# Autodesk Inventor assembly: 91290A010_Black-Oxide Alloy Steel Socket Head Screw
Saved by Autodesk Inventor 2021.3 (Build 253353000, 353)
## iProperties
Created: 2022-04
Part Number: 91290A010_Black-Oxide Alloy Steel Socket Head Screw
Document SubType Name: Assembly
Designer: Administrator
Title: 91290A010_Black-Oxide Alloy Steel Socket Head Screw v2
Author: Administrator
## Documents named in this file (2)
- c:\worker\convert-fusion-r02\tmp\job-1\57\output\files\f9e42cba-e390-44b0-9630-f24d5638462a\91290A010_Black-Oxide Alloy Steel Socket Head Screw v2.iam
- c:\worker\convert-fusion-r02\tmp\job-1\57\output\files\f9e42cba-e390-44b0-9630-f24d5638462a\Component1_1.ipt
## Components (1 placed, 1 different names)
1. Component1:1
